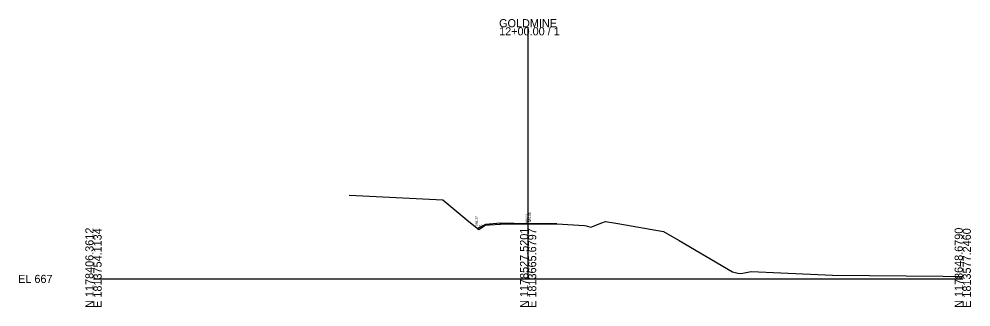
# Model space of a CAD drawing. Extents: x -26 to 1603, y -10 to 1590.
# Drawn here: x 1274.3 to 1602.8, y 1490.3 to 1589.7 of the extents above; entities that cross this region are included whole.
import ezdxf

# ---------------------------------------------------------------- set-up
doc = ezdxf.new("R2010")
doc.units = 0
for name, color, linetype in [('Default', 7, 'Continuous'), ('RD_GPK_XS_Cell', 7, 'Continuous'), ('RD_XS_EarthShd', 7, 'Continuous'), ('RD_XS_ExGround', 7, 'Continuous'), ('RD_XS_Misc_Line', 7, 'Continuous'), ('RD_XS_TieSlope', 7, 'Continuous'), ('RD_XS_TX_Elev_EX', 7, 'Continuous'), ('RD_XS_TX_Elev_PR', 7, 'Continuous'), ('RD_XS_TX_Slope', 7, 'Continuous')]:
    doc.layers.add(name, color=color, linetype=linetype)

msp = doc.modelspace()

# ---------------------------------------------------------------- linework, layer by layer
at = {"layer": 'Default'}
for p, q in [((1450, 1519.03), (1440.49, 1519.19)), ((1440.49, 1519.19), (1440.49, 1518.87)), ((1450, 1519.03), (1459.96, 1519.03)), ((1459.96, 1519.04), (1459.96, 1519.03))]:
    msp.add_line(p, q, dxfattribs=at)
at = {"layer": 'RD_GPK_XS_Cell'}
for p, q in [((1450, 1500), (1450, 1586.89)), ((1300, 1500), (1450, 1500)), ((1450, 1500), (1600, 1500))]:
    msp.add_line(p, q, dxfattribs=at)
at = {"layer": 'RD_XS_EarthShd'}
msp.add_line((1440.49, 1519.19), (1435.32, 1518.76), dxfattribs=at)
at = {"layer": 'RD_XS_ExGround'}
msp.add_lwpolyline([(1388.19, 1528.96), (1390.69, 1528.8), (1420.57, 1527.34), (1428.85, 1520.44), (1432.96, 1517.03), (1434.86, 1518.3), (1435.33, 1518.61), (1436.7, 1518.68), (1440.49, 1518.87), (1449.07, 1519.01), (1450, 1519.03), (1450.73, 1519.04), (1457.01, 1519.04), (1459.96, 1519.04), (1469.42, 1518.46), (1470.09, 1518.31), (1471.64, 1517.89), (1475.43, 1519.37), (1476.66, 1519.87), (1481.01, 1519.14), (1496.71, 1516.42), (1502.11, 1513.3), (1520.52, 1502.43), (1522.4, 1502.03), (1523.37, 1501.83), (1524.12, 1501.97), (1527.02, 1502.51), (1537.18, 1502.08), (1555.05, 1501.33), (1593.2, 1500.91), (1600, 1500.87)], dxfattribs=at)
at = {"layer": 'RD_XS_Misc_Line'}
for points in [[(1434.86, 1518.3), (1435.33, 1518.61), (1436.7, 1518.68), (1440.49, 1518.87), (1440.49, 1519.19), (1435.32, 1518.76), (1432.55, 1517.37), (1432.96, 1517.03)], [(1450, 1519.03), (1440.49, 1519.19), (1440.49, 1518.87), (1449.07, 1519.01)], [(1457.01, 1519.04), (1459.96, 1519.04), (1459.96, 1519.03), (1450, 1519.03), (1450.73, 1519.04)]]:
    msp.add_lwpolyline(points, close=True, dxfattribs=at)
at = {"layer": 'RD_XS_TieSlope'}
msp.add_line((1435.32, 1518.76), (1432.55, 1517.37), dxfattribs=at)

# ---------------------------------------------------------------- texts
at = {"layer": 'Default'}
msp.add_text('686.03', height=0.8, rotation=90, dxfattribs=at).set_placement((1451.01, 1519.56))
at = {"layer": 'RD_GPK_XS_Cell'}
for s, p in [('GOLDMINE', (1440, 1586.89)), ('12+00.00 / 1', (1440, 1584.09)), ('EL 667', (1274, 1498.6))]:
    msp.add_text(s, height=2.8, dxfattribs=at).set_placement(p)
for s, p in [('N 1178406.3612', (1300, 1490)), ('E 1813754.1134', (1302.8, 1490)), ('N 1178527.5201', (1450, 1490)), ('E 1813665.6797', (1452.8, 1490)), ('N 1178648.6790', (1600, 1490)), ('E 1813577.2460', (1602.8, 1490))]:
    msp.add_text(s, height=2.8, rotation=90, dxfattribs=at).set_placement(p)
at = {"layer": 'RD_XS_TX_Elev_EX'}
msp.add_text('686.03', height=0.75, rotation=90, dxfattribs=at).set_placement((1449.95, 1519.22))
at = {"layer": 'RD_XS_TX_Elev_PR'}
msp.add_text('684.37', height=0.8, rotation=90, dxfattribs=at).set_placement((1432.64, 1518.27))
at = {"layer": 'RD_XS_TX_Slope'}
msp.add_text('2:1', height=0.75, rotation=26.7003, dxfattribs=at).set_placement((1433.23, 1517.78))

doc.saveas('drawing.dxf')
